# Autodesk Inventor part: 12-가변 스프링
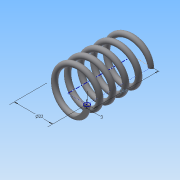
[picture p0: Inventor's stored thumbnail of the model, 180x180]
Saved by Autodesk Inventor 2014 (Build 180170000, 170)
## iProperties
Created: 2015-09
Part Number: 12-가변 스프링
Material: 강철, 탄소
Document SubType Name: Modeling
Designer: study
Density: 7.87 g/cm^3
Appearance: 반연마
Mass: 18.8856 g
Surface Area: 32.5491 cm^2
Volume: 2.3997 cm^3
Author: study
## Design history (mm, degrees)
sketch "스케치1"
  geometry: L1 (0, 0)-(11, 0); L2 (11, 0)-(11, 36.411); L3 (11, 36.411)-(0, 36.411); L4 (0, 36.411)-(0, 0); C1 r 1.5 at (11, 0)
  constraints: 8 end point, 2 parallel, 1 centre point, 1 coincident, 1 horizontal, 1 perpendicular
  dimensions: "d0" = 22 diameter of L2 L4; "d1" = 36.4112 distance of L1.end L2.end (derived); "d2" = 3 diameter of C1
feature "코일1" sketch "스케치1" pitch "d3" = 10; turns "d5" = 5; dims "d4" = 36.4112 (= d1), "d6" = 0, angle "d7" = 90 deg, angle "d8" = 90 deg, "d9" = 0, "d10" = 0
node "작업 평면1"
sketch "스케치2"
  geometry: L1 (-12.5, 0)-(-9.5, 0) reference; 1 further point
  constraints: 1 horizontal alignment
extrude "돌출1" cut sketch "스케치2" stored distance "d12" = 10; taper "d13" = 0 deg
node "작업 평면2"
sketch "스케치3"
  geometry: L1 (-9.5, 0)-(-12.5, 0) reference; 1 further point
  constraints: 1 horizontal alignment
extrude "돌출2" cut sketch "스케치3" stored distance "d15" = 10; taper "d16" = 0 deg
node "솔리드1"
node "절단 모서리 투영1"
node "절단 모서리 투영2"
other parameters: "d11" = 0, "d14" = 36.4112 (= d1)
